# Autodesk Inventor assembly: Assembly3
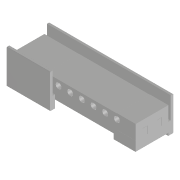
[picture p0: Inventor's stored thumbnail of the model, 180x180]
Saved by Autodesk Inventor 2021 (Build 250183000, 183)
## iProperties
Created: 2026-04
Part Number: Assembly3
Document SubType Name: Assembly
Designer: JCBG
Author: JCBG
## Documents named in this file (5)
- U:\Proyectos\203-24 (WENUS)\DOC\WP3. Training content\A3.3 Definition and Development of 3DP Exercises and videos\EJERCICIOS\3_Ventilated Door Frame\Assembly3.iam
- U:\Proyectos\203-24 (WENUS)\DOC\WP3. Training content\A3.3 Definition and Development of 3DP Exercises and videos\EJERCICIOS\3_Ventilated Door Frame\1.ipt
- U:\Proyectos\203-24 (WENUS)\DOC\WP3. Training content\A3.3 Definition and Development of 3DP Exercises and videos\EJERCICIOS\3_Ventilated Door Frame\2.ipt
- U:\Proyectos\203-24 (WENUS)\DOC\WP3. Training content\A3.3 Definition and Development of 3DP Exercises and videos\EJERCICIOS\3_Ventilated Door Frame\3.ipt
- U:\Proyectos\203-24 (WENUS)\DOC\WP3. Training content\A3.3 Definition and Development of 3DP Exercises and videos\EJERCICIOS\3_Ventilated Door Frame\4.ipt
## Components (4 placed, 4 different names)
1. 1:1 — Flush:2, Mate:6, Mate:7
2. 2:1 — Mate:1, Mate:2, Mate:5, Flush:2, Mate:6
3. 3:1 — Flush:1, Mate:3, Mate:4, Mate:5
4. 4:1 — Mate:1, Mate:2, Flush:1, Mate:3, Mate:4, Mate:7
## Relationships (9: Mate 7, Flush 2)
- Mate:1: 2:1 ↔ 4:1
- Mate:2: 2:1 ↔ 4:1
- Flush:1: 3:1 ↔ 4:1
- Mate:3: 3:1 ↔ 4:1
- Mate:4: 3:1 ↔ 4:1
- Mate:5: 2:1 ↔ 3:1
- Flush:2: 1:1 ↔ 2:1
- Mate:6: 1:1 ↔ 2:1
- Mate:7: 1:1 ↔ 4:1
